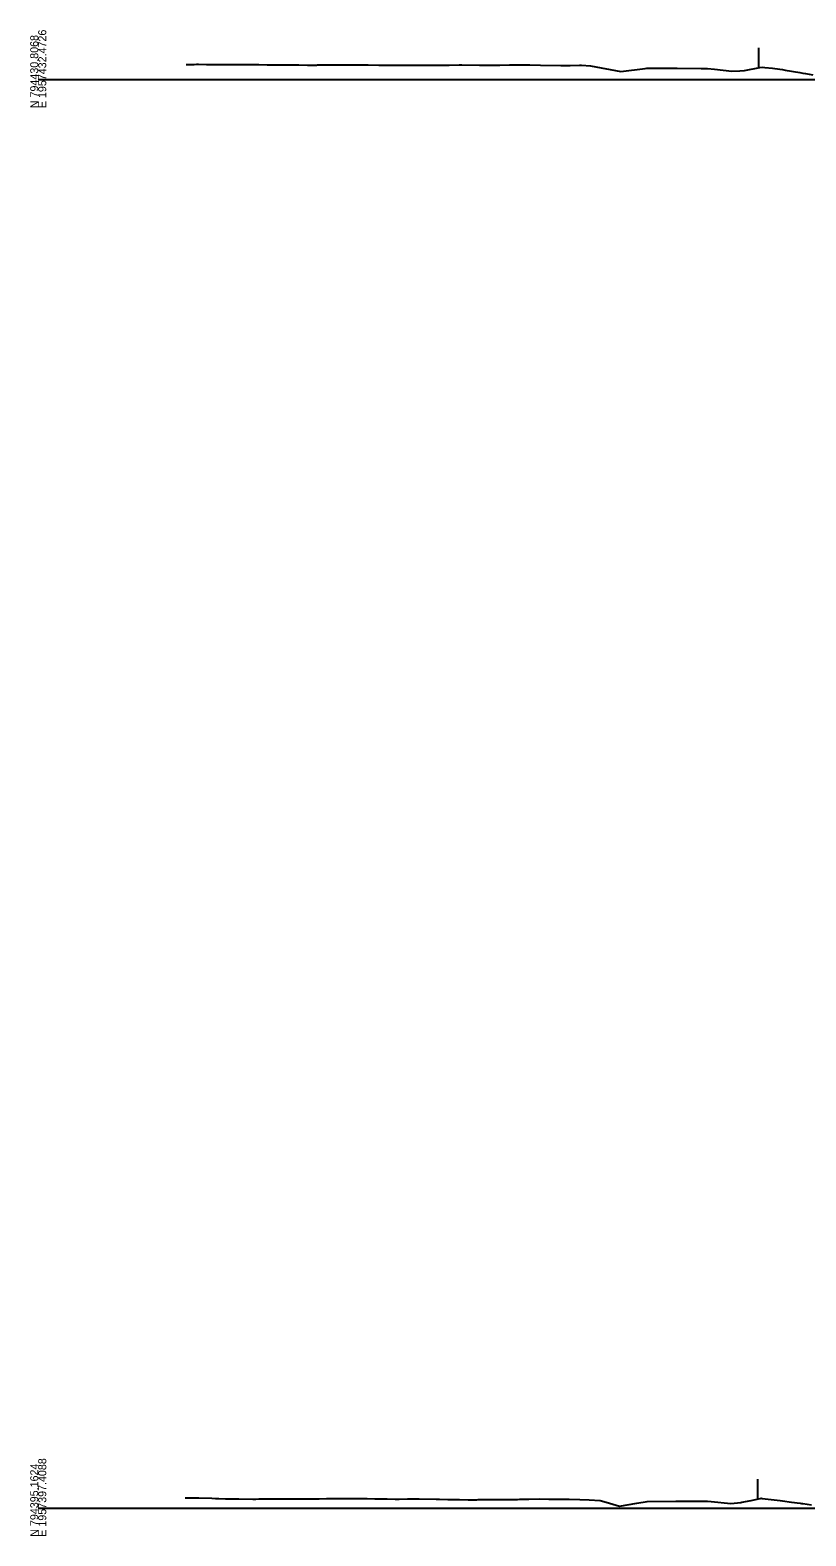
# Model space of a CAD drawing. Extents: x -4026 to 9638, y -10 to 19609.
# Drawn here: x -3003 to -2731, y 12490 to 13017 of the extents above; entities that cross this region are included whole.
import ezdxf

# ---------------------------------------------------------------- set-up
doc = ezdxf.new("R2010")
doc.units = 0
for name, color, linetype in [('Default', 7, 'Continuous'), ('RD_EX_Fence_Other', 7, 'Continuous'), ('RD_GPK_XS_Cell', 7, 'Continuous'), ('RD_XS_ExGround', 7, 'Continuous')]:
    doc.layers.add(name, color=color, linetype=linetype)

msp = doc.modelspace()

# ---------------------------------------------------------------- linework, layer by layer
at = {"layer": 'RD_EX_Fence_Other'}
for p, q in [((-2748.05, 13011.13), (-2748.05, 13004.13)), ((-2748.34, 12510.21), (-2748.34, 12503.21))]:
    msp.add_line(p, q, dxfattribs=at)
at = {"layer": 'RD_GPK_XS_Cell'}
for p, q in [((-3000, 13000), (-2650, 13000)), ((-3000, 12500), (-2650, 12500))]:
    msp.add_line(p, q, dxfattribs=at)
at = {"layer": 'RD_XS_ExGround'}
for points in [[(-2948.21, 13005.25), (-2945.45, 13005.33), (-2944.68, 13005.35), (-2943.92, 13005.35), (-2941.14, 13005.32), (-2938.32, 13005.31), (-2936.91, 13005.29), (-2931.19, 13005.26), (-2929.89, 13005.26), (-2927, 13005.27), (-2924.06, 13005.26), (-2922.88, 13005.25), (-2919.93, 13005.2), (-2916.93, 13005.19), (-2916.39, 13005.18), (-2915.87, 13005.18), (-2912.86, 13005.14), (-2909.8, 13005.15), (-2909.32, 13005.14), (-2908.85, 13005.13), (-2905.79, 13005.07), (-2902.67, 13005.11), (-2902.25, 13005.12), (-2901.84, 13005.12), (-2898.71, 13005.13), (-2895.54, 13005.14), (-2894.83, 13005.14), (-2891.64, 13005.17), (-2888.41, 13005.19), (-2887.81, 13005.19), (-2884.57, 13005.15), (-2880.8, 13005.09), (-2873.78, 13005.07), (-2866.77, 13005.06), (-2863.36, 13005.05), (-2859.76, 13005.1), (-2856.29, 13005.09), (-2852.74, 13005.17), (-2851.83, 13005.16), (-2845.63, 13005.1), (-2838.5, 13005.1), (-2835.07, 13005.15), (-2831.37, 13005.16), (-2828, 13005.17), (-2824.24, 13005.05), (-2817.11, 13004.94), (-2813.86, 13004.97), (-2810.66, 13005.02), (-2810.32, 13005.02), (-2809.98, 13005.01), (-2806.79, 13004.86), (-2796.15, 13002.79), (-2787.61, 13003.89), (-2787.08, 13003.96), (-2786.23, 13003.97), (-2776.5, 13004.04), (-2768.04, 13003.92), (-2765.8, 13003.88), (-2763.39, 13003.65), (-2757.29, 13003.01), (-2754.55, 13003.04), (-2752.94, 13003.23), (-2747.54, 13004.23), (-2746.68, 13004.33), (-2745.81, 13004.24), (-2743.15, 13004), (-2740.52, 13003.65), (-2739.61, 13003.52), (-2738.68, 13003.36), (-2733.51, 13002.48), (-2732.54, 13002.31), (-2731.55, 13002.12), (-2729, 13001.63)], [(-2948.62, 12503.68), (-2946.37, 12503.67), (-2943.83, 12503.6), (-2939.24, 12503.46), (-2938.02, 12503.43), (-2936.82, 12503.38), (-2934.48, 12503.3), (-2932.11, 12503.31), (-2930.95, 12503.3), (-2929.81, 12503.28), (-2924.98, 12503.2), (-2923.87, 12503.21), (-2922.79, 12503.22), (-2917.85, 12503.23), (-2916.8, 12503.24), (-2915.78, 12503.25), (-2913.27, 12503.26), (-2910.72, 12503.26), (-2909.73, 12503.26), (-2908.76, 12503.27), (-2903.59, 12503.28), (-2902.66, 12503.28), (-2901.75, 12503.3), (-2899.13, 12503.39), (-2896.46, 12503.38), (-2895.59, 12503.38), (-2894.74, 12503.39), (-2889.33, 12503.41), (-2888.52, 12503.41), (-2887.72, 12503.39), (-2884.98, 12503.35), (-2882.2, 12503.3), (-2880.71, 12503.28), (-2877.91, 12503.26), (-2875.07, 12503.17), (-2874.38, 12503.16), (-2873.7, 12503.17), (-2870.84, 12503.22), (-2867.94, 12503.25), (-2867.3, 12503.25), (-2866.68, 12503.24), (-2860.81, 12503.12), (-2860.23, 12503.11), (-2859.67, 12503.1), (-2856.7, 12503.07), (-2853.68, 12503.01), (-2853.16, 12503.01), (-2852.65, 12502.99), (-2849.63, 12502.95), (-2846.55, 12502.98), (-2846.09, 12503), (-2845.64, 12502.99), (-2839.42, 12503.06), (-2838.63, 12503.06), (-2835.48, 12503.08), (-2832.29, 12503.09), (-2831.61, 12503.1), (-2828.41, 12503.17), (-2824.6, 12503.22), (-2821.34, 12503.2), (-2817.59, 12503.15), (-2814.27, 12503.13), (-2810.57, 12503.03), (-2807.2, 12502.96), (-2803.35, 12502.67), (-2801.3, 12502.06), (-2796.66, 12500.7), (-2790.62, 12501.74), (-2787.01, 12502.36), (-2776.92, 12502.47), (-2776.56, 12502.47), (-2765.88, 12502.45), (-2764.6, 12502.33), (-2757.7, 12501.64), (-2754.16, 12501.97), (-2753.86, 12502.05), (-2750.63, 12502.73), (-2747.45, 12503.39), (-2747.09, 12503.45), (-2746.73, 12503.41), (-2740.43, 12502.65), (-2739.6, 12502.53), (-2736.49, 12502.1), (-2733.42, 12501.73), (-2732.95, 12501.68), (-2732.47, 12501.61), (-2729.41, 12501.18)]]:
    msp.add_lwpolyline(points, dxfattribs=at)

# ---------------------------------------------------------------- texts
at = {"layer": 'Default'}
for p in [(-3000, 13000), (-3000, 12500)]:
    msp.add_text('-', height=0.0001, dxfattribs=at).set_placement(p)
at = {"layer": 'RD_GPK_XS_Cell'}
for s, p in [('E 1957432.4726', (-2997.2, 12990)), ('N 794430.8068', (-3000, 12990)), ('E 1957397.4088', (-2997.2, 12490)), ('N 794395.1624', (-3000, 12490))]:
    msp.add_text(s, height=2.8, rotation=90, dxfattribs=at).set_placement(p)

doc.saveas('drawing.dxf')
